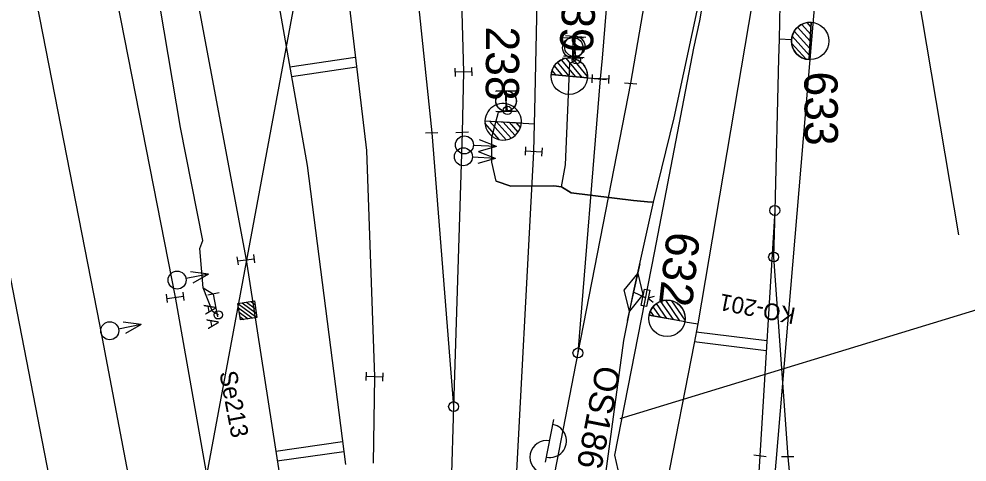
# Model space of a CAD drawing. Extents: x -545846 to -545044, y -1122650 to -1119108.
# Drawn here: x -545438.5 to -545381.4, y -1120243 to -1120216.4 of the extents above; entities that cross this region are included whole.
import ezdxf

# ---------------------------------------------------------------- set-up
doc = ezdxf.new("R2010")
doc.units = 0
for name, color, linetype in [('osvětlené plochy-hodnota-obrys', 7, 'Continuous'), ('Vrstva 1', 7, 'Continuous'), ('Vrstva 2', 7, 'Continuous'), ('Vrstva 25', 7, 'Continuous'), ('Vrstva 26', 7, 'Continuous'), ('Vrstva 27', 7, 'Continuous'), ('Vrstva 28 - zabzar', 7, 'Continuous'), ('Vrstva 3', 7, 'Continuous'), ('Vrstva 3 - Lisy - Pocitaci body', 7, 'Continuous'), ('Vrstva 31', 7, 'Continuous'), ('Vrstva 35', 7, 'Continuous'), ('Vrstva 51', 7, 'Continuous'), ('Vrstva 6 - Navesti', 7, 'Continuous'), ('Vrstva 63', 7, 'Continuous'), ('Vrstva 7', 7, 'Continuous')]:
    doc.layers.add(name, color=color, linetype=linetype)

msp = doc.modelspace()

# ---------------------------------------------------------------- linework, layer by layer
at = {"layer": 'osvětlené plochy-hodnota-obrys'}
for points in [[(-545398.15, -1120102.163), (-545405.365, -1120126.289), (-545451.846, -1120376.212), (-545451.085, -1120446.349), (-545447.102, -1120529.01)], [(-545397.928, -1120102.854), (-545393.734, -1120124.857), (-545389.026, -1120196.694), (-545397.237, -1120293.846), (-545425.658, -1120413.558)]]:
    msp.add_lwpolyline(points, dxfattribs=at)
at = {"layer": 'Vrstva 1'}
for p, q in [((-545392.702, -1120215.491), (-545392.754, -1120217.577)), ((-545403.509, -1120219.966), (-545404.854, -1120236.455)), ((-545413.653, -1120223.215), (-545412.338, -1120239.684)), ((-545393.011, -1120227.876), (-545393.905, -1120242.649))]:
    msp.add_line(p, q, dxfattribs=at)
for points in [[(-545396.964, -1120187.083), (-545398.609, -1120202.265), (-545401.684, -1120220.222)], [(-545418.498, -1120187.953), (-545415.308, -1120207.262), (-545413.653, -1120223.215)], [(-545413.975, -1120187.465), (-545412.186, -1120203.768), (-545411.752, -1120219.546), (-545411.819, -1120223.187)], [(-545401.294, -1120192.943), (-545402.641, -1120209.373), (-545403.404, -1120218.717), (-545403.509, -1120219.966)], [(-545426.936, -1120194.409), (-545423.867, -1120210.137), (-545423.127, -1120213.911), (-545421.145, -1120225.167), (-545418.84, -1120243.163)], [(-545431.588, -1120195.494), (-545428.418, -1120211.711), (-545424.828, -1120230.848), (-545421.515, -1120252.206), (-545419.7, -1120268.287)], [(-545436.282, -1120196.285), (-545433.022, -1120213.05), (-545429.085, -1120233.106), (-545425.425, -1120253.879), (-545424.036, -1120268.734), (-545423.749, -1120281.011), (-545423.869, -1120286.802)], [(-545406.905, -1120196.005), (-545407.264, -1120212.513), (-545407.472, -1120221.886), (-545407.484, -1120222.658)], [(-545440.917, -1120197.418), (-545437.59, -1120214.526), (-545433.638, -1120234.748), (-545429.782, -1120255.108), (-545427.618, -1120269.01), (-545425.542, -1120286.76)], [(-545445.553, -1120198.39), (-545442.178, -1120215.766), (-545438.596, -1120234.052), (-545433.023, -1120262.752), (-545430.646, -1120277.904), (-545429.369, -1120293.55), (-545429.108, -1120307.546), (-545429.408, -1120317.397), (-545430.786, -1120337.552)], [(-545421.337, -1120198.338), (-545419.415, -1120208.915), (-545417.585, -1120224.266), (-545417.104, -1120237.882), (-545417.177, -1120243.084)], [(-545394.375, -1120215.385), (-545397.648, -1120234.707), (-545397.87, -1120235.861), (-545399.524, -1120244.359), (-545402.417, -1120259.248)], [(-545392.754, -1120217.577), (-545392.784, -1120218.734), (-545393.011, -1120227.876), (-545393.081, -1120230.68), (-545392.23, -1120242.703)], [(-545401.684, -1120220.222), (-545404.854, -1120236.455), (-545406.656, -1120245.655), (-545406.887, -1120246.863)], [(-545407.484, -1120222.658), (-545407.524, -1120224.333), (-545408.713, -1120246.602)], [(-545411.819, -1120223.187), (-545412.338, -1120239.684), (-545412.633, -1120249.054), (-545412.672, -1120250.277)], [(-545393.905, -1120242.649), (-545394.665, -1120254.948), (-545394.971, -1120265.524), (-545393.66, -1120286.78)], [(-545392.23, -1120242.703), (-545391.041, -1120255.431), (-545388.616, -1120269.842)]]:
    msp.add_lwpolyline(points, dxfattribs=at)
at = {"layer": 'Vrstva 2'}
for p, q in [((-545391.641, -1120216.854), (-545390.883, -1120217.7)), ((-545391.392, -1120216.681), (-545390.86, -1120217.276)), ((-545391.083, -1120216.576), (-545390.836, -1120216.853)), ((-545390.944, -1120218.804), (-545390.82, -1120216.557)), ((-545390.82, -1120216.557), (-545390.944, -1120218.804)), ((-545392.005, -1120217.618), (-545392.754, -1120217.577)), ((-545391.966, -1120217.39), (-545390.93, -1120218.547)), ((-545391.835, -1120217.087), (-545390.906, -1120218.124)), ((-545391.999, -1120217.803), (-545391.128, -1120218.776)), ((-545404.595, -1120219.87), (-545405.555, -1120218.718)), ((-545404.276, -1120219.813), (-545405.187, -1120218.719)), ((-545405.784, -1120219.761), (-545406.271, -1120219.176)), ((-545405.388, -1120219.797), (-545406.081, -1120218.965)), ((-545404.991, -1120219.834), (-545405.844, -1120218.81)), ((-545404.278, -1120219.898), (-545406.464, -1120219.699)), ((-545406.464, -1120219.699), (-545404.278, -1120219.898)), ((-545406.18, -1120219.725), (-545406.409, -1120219.45)), ((-545404.278, -1120219.898), (-545404.278, -1120219.898)), ((-545404.277, -1120219.898), (-545403.509, -1120219.966)), ((-545403.509, -1120219.966), (-545404.854, -1120236.455)), ((-545403.883, -1120219.935), (-545403.135, -1120219.997)), ((-545402.058, -1120220.191), (-545401.31, -1120220.253)), ((-545410.453, -1120222.482), (-545408.262, -1120222.614)), ((-545410.453, -1120222.483), (-545410.453, -1120222.482)), ((-545410.451, -1120222.489), (-545407.484, -1120222.658)), ((-545409.569, -1120223.624), (-545410.45, -1120222.631)), ((-545409.183, -1120223.63), (-545410.186, -1120222.498)), ((-545408.884, -1120223.536), (-545409.784, -1120222.522)), ((-545408.643, -1120223.378), (-545409.381, -1120222.546)), ((-545408.452, -1120223.165), (-545408.979, -1120222.571)), ((-545408.316, -1120222.889), (-545408.576, -1120222.595)), ((-545413.278, -1120223.202), (-545414.028, -1120223.228)), ((-545413.653, -1120223.215), (-545412.338, -1120239.684)), ((-545411.444, -1120223.174), (-545412.194, -1120223.2)), ((-545399.504, -1120234.371), (-545400.12, -1120233.481)), ((-545399.112, -1120234.443), (-545399.871, -1120233.348)), ((-545398.721, -1120234.514), (-545399.574, -1120233.282)), ((-545398.398, -1120234.487), (-545399.208, -1120233.316)), ((-545400.287, -1120234.229), (-545400.49, -1120233.935)), ((-545399.895, -1120234.3), (-545400.329, -1120233.674)), ((-545398.408, -1120234.571), (-545400.567, -1120234.178)), ((-545400.567, -1120234.178), (-545398.408, -1120234.57)), ((-545398.408, -1120234.57), (-545398.408, -1120234.571)), ((-545398.407, -1120234.571), (-545397.648, -1120234.707)), ((-545393.533, -1120242.699), (-545394.277, -1120242.599)), ((-545391.855, -1120242.711), (-545392.605, -1120242.695))]:
    msp.add_line(p, q, dxfattribs=at)
for points in [[(-545401.294, -1120192.943), (-545402.641, -1120209.373), (-545403.404, -1120218.717), (-545403.509, -1120219.966)], [(-545406.905, -1120196.005), (-545407.264, -1120212.513), (-545407.472, -1120221.886), (-545407.484, -1120222.658)], [(-545392.754, -1120217.577), (-545392.784, -1120218.734), (-545393.011, -1120227.876), (-545393.905, -1120242.649)], [(-545401.684, -1120220.222), (-545404.854, -1120236.455), (-545406.656, -1120245.655), (-545406.887, -1120246.863)], [(-545411.819, -1120223.187), (-545412.338, -1120239.684), (-545412.633, -1120249.054), (-545412.672, -1120250.277)], [(-545393.011, -1120227.876), (-545393.081, -1120230.68), (-545392.23, -1120242.703)], [(-545397.648, -1120234.707), (-545397.87, -1120235.861), (-545399.524, -1120244.359), (-545402.417, -1120259.248)]]:
    msp.add_lwpolyline(points, dxfattribs=at)
for centre, radius in [((-545390.882, -1120217.68), 1.125), ((-545405.377, -1120219.797), 1.097), ((-545393.011, -1120227.876), 0.3), ((-545393.081, -1120230.68), 0.3), ((-545399.493, -1120234.372), 1.097), ((-545404.854, -1120236.455), 0.3), ((-545412.338, -1120239.684), 0.3)]:
    msp.add_circle(centre, radius, dxfattribs=at)
for centre, radius, start, end in [((-545390.882, -1120217.68), 1.125, 86.8359, 266.8359), ((-545405.371, -1120219.799), 1.098, 354.8262, 174.7871), ((-545409.356, -1120222.547), 1.097, 356.5162, 176.9857), ((-545409.357, -1120222.548), 1.098, 176.6057, 356.5665), ((-545399.488, -1120234.374), 1.098, 349.7129, 169.6738)]:
    msp.add_arc(centre, radius, start, end, dxfattribs=at)
at = {"layer": 'Vrstva 25'}
msp.add_line((-545406.805, -1120243.017), (-545406.307, -1120240.465), dxfattribs=at)
for centre, start, end in [((-545406.544, -1120241.743), 258.2389, 79.6441), ((-545406.748, -1120242.722), 78.9415, 258.9415)]:
    msp.add_arc(centre, 1, start, end, dxfattribs=at)
at = {"layer": 'Vrstva 26'}
msp.add_lwpolyline([(-545395.06, -1120201.08), (-545395.42, -1120203.85), (-545397.55, -1120216.46), (-545397.91, -1120218.12), (-545400.25, -1120230.32), (-545402.65, -1120242.6), (-545402.25, -1120244.37), (-545402.46, -1120245.74), (-545403.05, -1120245.1), (-545403.05, -1120244.67), (-545403.014, -1120244.471)], dxfattribs=at)
at = {"layer": 'Vrstva 27'}
for p, q in [((-545404.962, -1120218.835), (-545404.958, -1120218.785)), ((-545409.101, -1120221.885), (-545409.099, -1120221.835)), ((-545400.534, -1120232.671), (-545400.531, -1120232.674)), ((-545426.496, -1120234.185), (-545426.504, -1120234.135))]:
    msp.add_line(p, q, dxfattribs=at)
msp.add_lwpolyline([(-545400.531, -1120232.671), (-545400.722, -1120233.653), (-545401.049, -1120233.589), (-545400.858, -1120232.607)], close=True, dxfattribs=at)
msp.add_lwpolyline([(-545400.267, -1120233.062), (-545400.626, -1120233.162), (-545400.331, -1120233.389)], dxfattribs=at)
for centre in [(-545404.96, -1120218.81), (-545409.1, -1120221.86), (-545426.5, -1120234.16)]:
    msp.add_circle(centre, 0.25, dxfattribs=at)
at = {"layer": 'Vrstva 28 - zabzar'}
for p, q in [((-545409.1, -1120221.86), (-545409.17, -1120221.3)), ((-545401.133, -1120231.096), (-545401.887, -1120234.504)), ((-545402.078, -1120232.674), (-545401.259, -1120231.664)), ((-545401.259, -1120231.664), (-545400.942, -1120232.926)), ((-545401.761, -1120233.936), (-545402.078, -1120232.674)), ((-545400.942, -1120232.926), (-545401.761, -1120233.936)), ((-545400.79, -1120233.13), (-545401.51, -1120232.8))]:
    msp.add_line(p, q, dxfattribs=at)
for points in [[(-545411.75, -1120288.1), (-545410.36, -1120282.42), (-545408.45, -1120271.99), (-545406.79, -1120262.46), (-545405.51, -1120253.66), (-545405.06, -1120252.08), (-545403.89, -1120247.67), (-545403.42, -1120245.47), (-545403.34, -1120244.9), (-545402.09, -1120235.71), (-545401.51, -1120232.8), (-545400.31, -1120227.37), (-545399.06, -1120222.3), (-545397.38, -1120214.45), (-545396.52, -1120209.73), (-545395.44, -1120203.99), (-545395.32, -1120202.59), (-545395.12, -1120200.9), (-545395.29, -1120198.49), (-545394.8, -1120190.22), (-545395.02, -1120189.55), (-545394.66, -1120189.01)], [(-545427.4, -1120232.53), (-545427.61, -1120230.17), (-545427.42, -1120229.69), (-545428.77, -1120222.88), (-545429.99, -1120215.65)], [(-545405.84, -1120226.46), (-545405.61, -1120225.14), (-545405.35, -1120219.02), (-545404.96, -1120218.81), (-545405.05, -1120218.01)], [(-545400.31, -1120227.37), (-545400.44, -1120227.39), (-545401.51, -1120227.28), (-545405.27, -1120226.81), (-545405.84, -1120226.46), (-545406.3, -1120226.4), (-545408.89, -1120226.41), (-545409.77, -1120226.11), (-545410.03, -1120224.97), (-545410.03, -1120223.46), (-545409.63, -1120221.97), (-545409.1, -1120221.86), (-545409.17, -1120221.3)], [(-545426.5, -1120234.16), (-545426.85, -1120233.96), (-545427.4, -1120232.53), (-545426.79, -1120232.91)]]:
    msp.add_lwpolyline(points, dxfattribs=at)
at = {"layer": 'Vrstva 3'}
for p, q in [((-545405.763, -1120217.464), (-545404.531, -1120217.488)), ((-545405.171, -1120218.708), (-545405.147, -1120217.476)), ((-545405.787, -1120218.696), (-545404.555, -1120218.72)), ((-545412.261, -1120219.314), (-545412.243, -1120219.813)), ((-545411.261, -1120219.279), (-545411.243, -1120219.778)), ((-545411.252, -1120219.528), (-545412.252, -1120219.564)), ((-545403.998, -1120219.694), (-545404.019, -1120220.194)), ((-545402.999, -1120219.738), (-545403.02, -1120220.238)), ((-545403.009, -1120219.988), (-545404.009, -1120219.944)), ((-545409.822, -1120220.696), (-545408.591, -1120220.653)), ((-545409.163, -1120221.906), (-545409.207, -1120220.674)), ((-545409.779, -1120221.927), (-545408.548, -1120221.884)), ((-545409.764, -1120224.035), (-545410.779, -1120223.635)), ((-545409.764, -1120224.035), (-545411.142, -1120223.961)), ((-545409.826, -1120224.755), (-545410.841, -1120224.355)), ((-545409.764, -1120224.035), (-545410.816, -1120224.324)), ((-545408.009, -1120224.055), (-545408.037, -1120224.554)), ((-545407.025, -1120224.362), (-545408.023, -1120224.304)), ((-545407.011, -1120224.112), (-545407.039, -1120224.611)), ((-545409.826, -1120224.755), (-545411.204, -1120224.681)), ((-545409.826, -1120224.755), (-545410.878, -1120225.044)), ((-545425.292, -1120231.159), (-545425.356, -1120230.664)), ((-545424.3, -1120231.032), (-545424.364, -1120230.537)), ((-545425.324, -1120230.912), (-545424.332, -1120230.784)), ((-545427.084, -1120231.718), (-545428.44, -1120231.972)), ((-545427.084, -1120231.718), (-545428.165, -1120231.57)), ((-545427.084, -1120231.718), (-545428.038, -1120232.248)), ((-545429.549, -1120233.417), (-545429.613, -1120232.922)), ((-545428.557, -1120233.29), (-545428.621, -1120232.795)), ((-545429.581, -1120233.17), (-545428.589, -1120233.042)), ((-545431.14, -1120234.748), (-545432.222, -1120234.609)), ((-545431.14, -1120234.748), (-545432.494, -1120235.014)), ((-545431.14, -1120234.748), (-545432.089, -1120235.286)), ((-545417.594, -1120237.613), (-545417.613, -1120238.112)), ((-545416.604, -1120237.901), (-545417.604, -1120237.863)), ((-545416.595, -1120237.652), (-545416.614, -1120238.151))]:
    msp.add_line(p, q, dxfattribs=at)
for centre, radius in [((-545405.16, -1120218.09), 0.616), ((-545409.186, -1120221.288), 0.616), ((-545411.684, -1120223.931), 0.542), ((-545411.746, -1120224.651), 0.542), ((-545428.974, -1120232.071), 0.542), ((-545433.027, -1120235.116), 0.542)]:
    msp.add_circle(centre, radius, dxfattribs=at)
at = {"layer": 'Vrstva 3 - Lisy - Pocitaci body'}
for p, q in [((-545405.612, -1120217.345), (-545404.385, -1120217.448)), ((-545405.102, -1120218.624), (-545404.998, -1120217.396)), ((-545405.715, -1120218.572), (-545404.488, -1120218.675)), ((-545409.772, -1120220.67), (-545408.54, -1120220.698)), ((-545409.184, -1120221.916), (-545409.156, -1120220.684)), ((-545409.8, -1120221.902), (-545408.568, -1120221.93)), ((-545425.315, -1120233.479), (-545424.173, -1120234.314)), ((-545425.053, -1120233.439), (-545424.214, -1120234.052)), ((-545424.791, -1120233.398), (-545424.255, -1120233.79)), ((-545424.529, -1120233.357), (-545424.295, -1120233.528)), ((-545425.274, -1120233.741), (-545424.435, -1120234.355)), ((-545425.234, -1120234.003), (-545424.698, -1120234.395)), ((-545425.193, -1120234.265), (-545424.959, -1120234.436))]:
    msp.add_line(p, q, dxfattribs=at)
msp.add_lwpolyline([(-545424.327, -1120233.326), (-545424.173, -1120234.314), (-545425.162, -1120234.467), (-545425.315, -1120233.479)], close=True, dxfattribs=at)
for centre in [(-545405.05, -1120218.007), (-545409.171, -1120221.298)]:
    msp.add_circle(centre, 0.616, dxfattribs=at)
at = {"layer": 'Vrstva 31'}
msp.add_lwpolyline([(-545403.34, -1120244.9), (-545402.09, -1120235.71), (-545401.51, -1120232.8), (-545400.31, -1120227.37), (-545399.06, -1120222.3), (-545397.38, -1120214.45), (-545396.52, -1120209.73), (-545395.44, -1120203.99), (-545395.32, -1120202.59), (-545395.12, -1120200.9), (-545395.29, -1120198.49), (-545394.8, -1120190.22), (-545395.02, -1120189.55), (-545394.05, -1120189.14), (-545390.61, -1120189.25), (-545389.43, -1120189.09), (-545389.24, -1120187.33), (-545388.66, -1120186.67)], dxfattribs=at)
at = {"layer": 'Vrstva 35'}
for points in [[(-545409.77, -1120226.11), (-545408.89, -1120226.41), (-545406.3, -1120226.4), (-545405.84, -1120226.46)], [(-545405.84, -1120226.46), (-545405.27, -1120226.81), (-545401.51, -1120227.28), (-545400.44, -1120227.39)]]:
    msp.add_lwpolyline(points, dxfattribs=at)
at = {"layer": 'Vrstva 51'}
msp.add_lwpolyline([(-545381.926, -1120229.34), (-545384.4, -1120214.695), (-545386.488, -1120187.748)], dxfattribs=at)
at = {"layer": 'Vrstva 6 - Navesti'}
for p, q in [((-545426.446, -1120232.845), (-545427.134, -1120232.975)), ((-545426.534, -1120234.272), (-545426.79, -1120232.91))]:
    msp.add_line(p, q, dxfattribs=at)
at = {"layer": 'Vrstva 63'}
msp.add_line((-545377.188, -1120232.736), (-545402.335, -1120240.427), dxfattribs=at)
at = {"layer": 'Vrstva 7'}
for p, q in [((-545418.252, -1120218.669), (-545422.187, -1120219.249)), ((-545418.181, -1120219.265), (-545422.083, -1120219.841)), ((-545397.738, -1120235.176), (-545393.485, -1120235.712)), ((-545397.852, -1120235.767), (-545393.521, -1120236.312)), ((-545419.014, -1120241.803), (-545423.04, -1120242.373)), ((-545418.938, -1120242.398), (-545422.948, -1120242.966))]:
    msp.add_line(p, q, dxfattribs=at)

# ---------------------------------------------------------------- texts
at = {"layer": 'Vrstva 2'}
for s, rotation, p in [('239', 266.3446, (-545405.692, -1120213.848)), ('238', 269.7646, (-545410.385, -1120216.804)), ('633', 270.4638, (-545391.236, -1120219.524)), ('632', 263.6088, (-545399.491, -1120229.1))]:
    msp.add_text(s, height=2, rotation=rotation, dxfattribs=at).set_placement(p)
at = {"layer": 'Vrstva 25'}
msp.add_text('OS186', height=1.5, rotation=258.9415, dxfattribs=at).set_placement((-545403.735, -1120237.134))
at = {"layer": 'Vrstva 27'}
msp.add_text('KO-201', height=1, rotation=168.986, dxfattribs=at).set_placement((-545391.704, -1120233.756))
at = {"layer": 'Vrstva 6 - Navesti'}
for s, height, p in [('  A A ', 0.7, (-545427.478, -1120233.039)), ('Se213', 1.05, (-545426.438, -1120237.63))]:
    msp.add_text(s, height=height, rotation=280.6249, dxfattribs=at).set_placement(p)

doc.saveas('drawing.dxf')
